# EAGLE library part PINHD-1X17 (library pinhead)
PIN HEADER
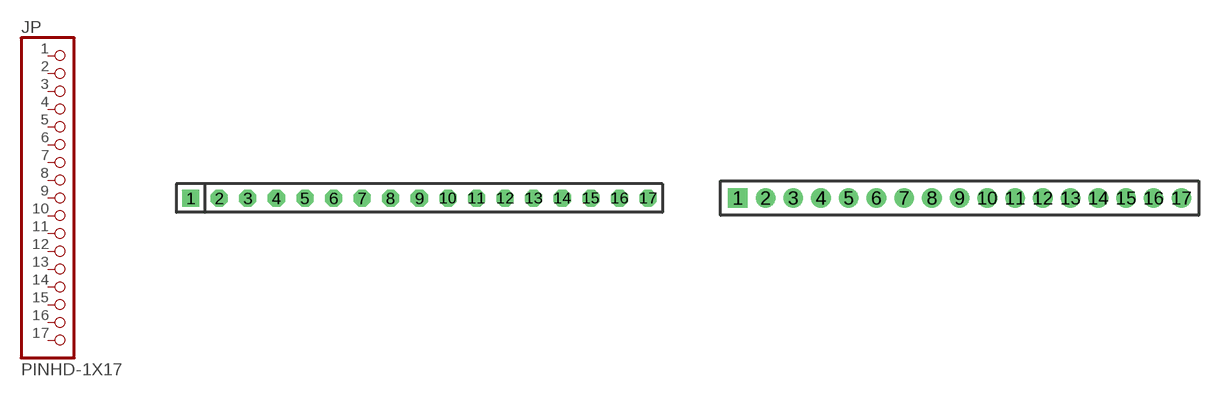
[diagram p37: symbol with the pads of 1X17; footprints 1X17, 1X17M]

Designator prefix JP

## PINHD-1X17  [1X17]
1  1  pas
2  2  pas
3  3  pas
4  4  pas
5  5  pas
6  6  pas
7  7  pas
8  8  pas
9  9  pas
10  10  pas
11  11  pas
12  12  pas
13  13  pas
14  14  pas
15  15  pas
16  16  pas
17  17  pas

## PINHD-1X17M  [1X17M]
Pads as for 1X17

## Footprint 1X17 (pad centres in mm)
PIN HEADER - 0.1"
drill 1.016 square: 1 -20.32,0
drill 1.016 octagon: 2 -17.78,0; 3 -15.24,0; 4 -12.7,0; 5 -10.16,0; 6 -7.62,0; 7 -5.08,0; 8 -2.54,0; 9 0,0; 10 2.54,0; 11 5.08,0; 12 7.62,0; 13 10.16,0; 14 12.7,0; 15 15.24,0; 16 17.78,0; 17 20.32,0

## Footprint 1X17M (pad centres in mm)
PIN HEADER - 2MM"
drill 0.914 square: 1 -16,0
drill 0.914 round: 2 -14,0; 3 -12,0; 4 -10,0; 5 -8,0; 6 -6,0; 7 -4,0; 8 -2,0; 9 0,0; 10 2,0; 11 4,0; 12 6,0; 13 8,0; 14 10,0; 15 12,0; 16 14,0; 17 16,0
